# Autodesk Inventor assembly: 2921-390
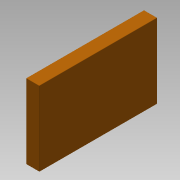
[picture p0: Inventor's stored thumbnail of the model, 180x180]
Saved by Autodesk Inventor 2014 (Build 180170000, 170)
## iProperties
Company: NHTSA/VRTC
Created: 2012-02
Part Number: 2921-390
Document SubType Name: Assembly
Designer: Mike Vanvoorhis
Project: CHILD SIDE IMPACT SLED
Description: SEAT BACK CUSHION ASS'Y.
Mass: 18636 g
Surface Area: 33686.9 cm^2
Volume: 26852.7 cm^3
Density: 0.694008 g/cm^3
Title: Seat Back Cushion Assembly
Subject: Child Side Impact Sled
Author: Dave Walker
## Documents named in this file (4)
- B:\VRTC_DWG\BIO\Non-P572\Child Side-Frontal Impact Sled\Side Impact Sled\Seat_Back_Cushion_Assembly.iam
- B:\VRTC_DWG\BIO\Non-P572\Child Side-Frontal Impact Sled\Side Impact Sled\Seat_Back_Cushion_Mounting_Plate_Assembly.iam
- B:\VRTC_DWG\BIO\Non-P572\Child Side-Frontal Impact Sled\Side Impact Sled\Seat_Back_Cushion.ipt
- B:\VRTC_DWG\BIO\Non-P572\Child Side-Frontal Impact Sled\Side Impact Sled\Seat_Back_Cushion_Cover.ipt
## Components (3 placed, 3 different names)
1. Seat_Back_Cushion_Mounting_Plate_Assembly:1 [sub-assembly] — Mate:1, Flush:2, Insert:1, Insert:2, Mate:2
2. Seat_Back_Cushion:1 — Mate:1, Flush:2, Mate:2
3. Seat_Back_Cushion_Cover:1 — Insert:1, Insert:2
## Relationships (5: Mate 2, Insert 2, Flush 1)
- Mate:1: Seat_Back_Cushion_Mounting_Plate_Assembly:1 ↔ Seat_Back_Cushion:1
- Flush:2: Seat_Back_Cushion_Mounting_Plate_Assembly:1 ↔ Seat_Back_Cushion:1
- Insert:1: Seat_Back_Cushion_Mounting_Plate_Assembly:1 ↔ Seat_Back_Cushion_Cover:1
- Insert:2: Seat_Back_Cushion_Mounting_Plate_Assembly:1 ↔ Seat_Back_Cushion_Cover:1
- Mate:2: Seat_Back_Cushion_Mounting_Plate_Assembly:1 ↔ Seat_Back_Cushion:1
